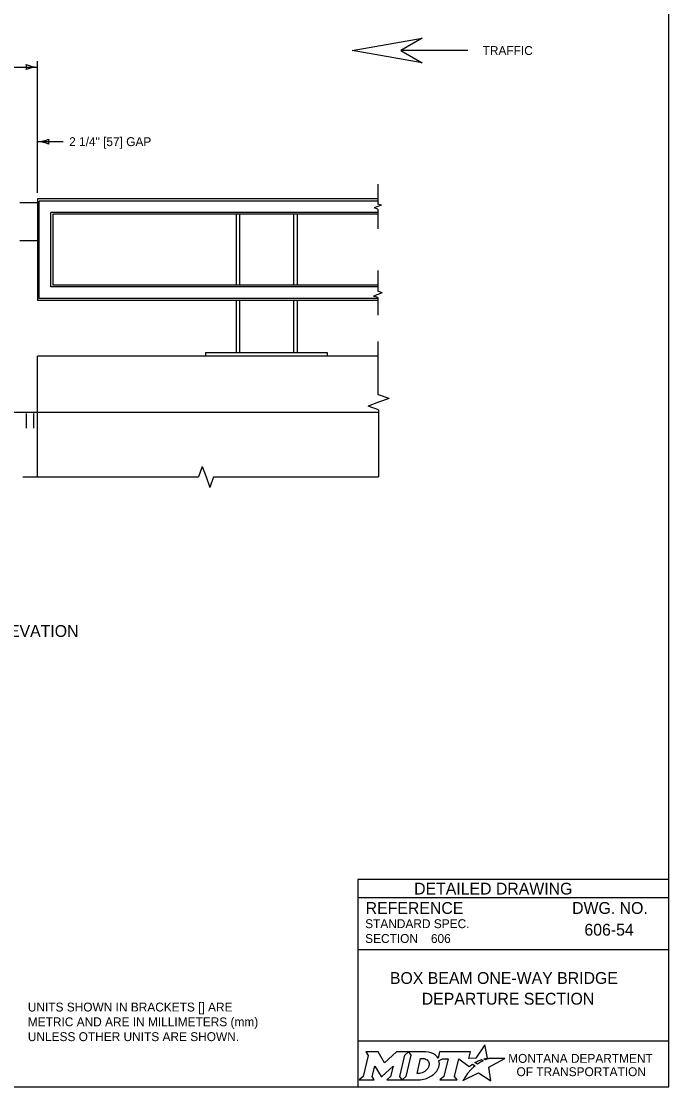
# Model space of a CAD drawing. Extents: x 49991.4 to 50021, y 49987.6 to 50011.4.
# Drawn here: x 50004.24 to 50008.61, y 50000.06 to 50007.26 of the extents above; entities that cross this region are included whole.
import ezdxf

# ---------------------------------------------------------------- set-up
doc = ezdxf.new("R2010")
doc.units = 0
for name, color, linetype in [('Level 1', 7, 'Continuous'), ('Level 2', 7, 'Continuous'), ('Level 3', 7, 'Continuous'), ('Level 4', 7, 'Continuous'), ('Level 6', 7, 'Continuous')]:
    doc.layers.add(name, color=color, linetype=linetype)

msp = doc.modelspace()

# ---------------------------------------------------------------- linework, layer by layer
at = {"layer": 'Level 1'}
for p, q in [((50007.2582, 50007.0589), (50006.8063, 50007.0589)), ((50007.2582, 50007.0585), (50006.8063, 50007.0585)), ((50006.6505, 50006.0572), (50004.3525, 50006.0572)), ((50004.3525, 50006.0572), (50004.3525, 50005.3714)), ((50004.3525, 50006.031), (50004.2333, 50006.031)), ((50004.4553, 50005.9543), (50004.4553, 50005.4743)), ((50006.6505, 50005.9543), (50004.4553, 50005.9543)), ((50005.6928, 50005.9543), (50005.6928, 50005.4743)), ((50005.7172, 50005.9543), (50005.7172, 50005.4743)), ((50006.0801, 50005.9543), (50006.0801, 50005.4743)), ((50006.1048, 50005.9543), (50006.1048, 50005.4743)), ((50004.3525, 50005.774), (50004.2333, 50005.774)), ((50006.6505, 50005.4743), (50004.4553, 50005.4743)), ((50006.6505, 50005.3714), (50004.3525, 50005.3714)), ((50005.6928, 50005.3714), (50005.6928, 50005.0209)), ((50005.7172, 50005.3714), (50005.7172, 50005.0209)), ((50006.0801, 50005.3714), (50006.0801, 50005.0209)), ((50006.1048, 50005.3714), (50006.1048, 50005.0209)), ((50006.6505, 50004.9951), (50004.3525, 50004.9951)), ((50004.3525, 50004.6177), (50004.3525, 50004.9951)), ((50005.4865, 50005.0209), (50006.3094, 50005.0209)), ((50005.4865, 50005.0209), (50005.4865, 50004.9951)), ((50006.3094, 50005.0209), (50006.3094, 50004.9951)), ((50001.9518, 50004.6177), (50006.6556, 50004.6177)), ((50004.279, 50004.5095), (50004.279, 50004.607)), ((50004.3278, 50004.5095), (50004.3278, 50004.607))]:
    msp.add_line(p, q, dxfattribs=at)
for points in [[(50008.6146, 50011.2628), (50000.3356, 50011.2628), (50000.3356, 50000.0624), (50008.6146, 50000.0624)], [(50006.9508, 50006.9751), (50006.4779, 50007.0585), (50006.9508, 50007.1423), (50006.8065, 50007.0585)]]:
    msp.add_lwpolyline(points, close=True, dxfattribs=at)
at = {"layer": 'Level 2'}
for p, q in [((50008.6146, 50001.4624), (50006.5146, 50001.4624)), ((50006.5146, 50001.4624), (50006.5146, 50000.0624)), ((50008.6146, 50001.3374), (50006.5146, 50001.3374)), ((50008.2507, 50001.1223), (50008.2507, 50001.1223)), ((50007.0089, 50001.0629), (50007.0089, 50001.0629)), ((50008.6146, 50000.9874), (50006.5146, 50000.9874)), ((50007.5646, 50000.7383), (50007.5646, 50000.7383)), ((50008.6146, 50000.3693), (50006.5146, 50000.3693))]:
    msp.add_line(p, q, dxfattribs=at)
for points in [[(50006.5701, 50000.2974), (50006.5842, 50000.274), (50006.5507, 50000.1307), (50006.525, 50000.1082), (50006.6266, 50000.1082), (50006.6131, 50000.131), (50006.6293, 50000.2011), (50006.673, 50000.1321), (50006.6783, 50000.1321), (50006.7534, 50000.2016), (50006.737, 50000.1305), (50006.7123, 50000.1085), (50006.8139, 50000.1085), (50006.8001, 50000.1318), (50006.8333, 50000.2742)], [(50006.8333, 50000.2742), (50006.8586, 50000.2974), (50006.7762, 50000.2974), (50006.6966, 50000.2244), (50006.6521, 50000.2971), (50006.5701, 50000.2974)], [(50006.9722, 50000.2974), (50006.8586, 50000.2974), (50006.8733, 50000.2745), (50006.8394, 50000.1307), (50006.8139, 50000.1085), (50006.9245, 50000.1085)], [(50007.3771, 50000.2447), (50007.3668, 50000.2503), (50007.3784, 50000.2531), (50007.39, 50000.2551), (50007.3726, 50000.3452), (50007.3131, 50000.2539), (50007.2658, 50000.2532), (50007.2761, 50000.2973), (50007.0669, 50000.2974), (50007.0568, 50000.2549), (50007.051, 50000.2632)], [(50006.9962, 50000.2107), (50006.995, 50000.2026), (50006.9918, 50000.1933), (50006.9876, 50000.1851), (50006.982, 50000.1776), (50006.9755, 50000.1707), (50006.9676, 50000.1644), (50006.9593, 50000.1597), (50006.9502, 50000.1558), (50006.9411, 50000.1535), (50006.9319, 50000.1526), (50006.916, 50000.1526), (50006.9396, 50000.2526), (50006.9556, 50000.2526), (50006.9632, 50000.252), (50006.9708, 50000.2501), (50006.9774, 50000.2471), (50006.9835, 50000.2429), (50006.9883, 50000.2379), (50006.992, 50000.2319), (50006.9947, 50000.2257), (50006.9963, 50000.2183), (50006.9963, 50000.2153), (50006.9962, 50000.2107)], [(50007.0636, 50000.2383), (50007.0882, 50000.2514), (50007.1251, 50000.2514), (50007.0965, 50000.1309), (50007.069, 50000.1082), (50007.1852, 50000.1082), (50007.1682, 50000.1311), (50007.1964, 50000.2513), (50007.2677, 50000.1996), (50007.2888, 50000.2147), (50007.3085, 50000.2038)], [(50007.2527, 50000.1479), (50007.2374, 50000.1235), (50007.2327, 50000.116), (50007.2269, 50000.1074), (50007.2246, 50000.1031), (50007.3299, 50000.1562), (50007.4138, 50000.1011), (50007.4007, 50000.1938), (50007.5076, 50000.2522), (50007.4583, 50000.253), (50007.4282, 50000.2534), (50007.4074, 50000.2537), (50007.4006, 50000.2522), (50007.3957, 50000.251), (50007.3873, 50000.2487), (50007.3771, 50000.2447)], [(50007.3267, 50000.2171), (50007.3243, 50000.2154), (50007.306, 50000.225), (50007.3163, 50000.2307), (50007.3204, 50000.2329), (50007.329, 50000.2369), (50007.3347, 50000.2395), (50007.3426, 50000.2425), (50007.3499, 50000.2452), (50007.3617, 50000.2378), (50007.3577, 50000.2357), (50007.3531, 50000.2332), (50007.3489, 50000.231), (50007.3439, 50000.2281), (50007.342, 50000.227), (50007.3393, 50000.2254), (50007.3368, 50000.224), (50007.3345, 50000.2224), (50007.3319, 50000.2206), (50007.3292, 50000.2188), (50007.3267, 50000.2171)], [(50007.2666, 50000.164), (50007.2666, 50000.164)], [(50006.9702, 50000.1158), (50006.9786, 50000.1184), (50006.9916, 50000.1238), (50007.012, 50000.1348)]]:
    msp.add_lwpolyline(points, dxfattribs=at)
for centre, radius, start, end in [((50006.9953, 50000.219), 0.0709, 339.53292, 15.85821), ((50006.9513, 50000.2363), 0.1183, 300.91025, 339.13831)]:
    msp.add_arc(centre, radius, start, end, dxfattribs=at)
for centre, major_axis, ratio, start_param, end_param in [((50006.9701, 50000.25), (0.0834, -0.0037), 0.568097, 0.61298, 1.570796), ((50007.0257, 50000.2573), (0.0361, -0.0295), 0.469099, 1.225588, 1.570796), ((50007.2597, 50000.1559), (-0.00694, -0.00806), 0.008222, 0, 3.137361), ((50007.2764, 50000.1742), (-0.0098, -0.0102), 0.016458, 3.141593, 6.279097), ((50007.2974, 50000.1941), (-0.0112, -0.0097), 0.021651, 3.157348, 6.283185), ((50006.9248, 50000.2568), (0, 0.1484), 0.987302, 3.139398, 3.456847)]:
    msp.add_ellipse(centre, major_axis=major_axis, ratio=ratio, start_param=start_param, end_param=end_param, dxfattribs=at)
at = {"layer": 'Level 3'}
for p, q in [((50004.3525, 50006.0972), (50004.3525, 50006.9869)), ((50002.4997, 50006.9469), (50004.3525, 50006.9469)), ((50004.3525, 50006.4436), (50004.5259, 50006.4436))]:
    msp.add_line(p, q, dxfattribs=at)
for centre, radius, start, end in [((50004.3617, 50007.1691), 0.2223, 247.45601, 267.63952), ((50004.2243, 50006.9469), 0.0548, 342.13882, 17.86118), ((50004.364, 50006.7142), 0.233, 92.82731, 112.07716), ((50004.3411, 50006.6763), 0.233, 272.82731, 292.07716), ((50004.3434, 50006.2214), 0.2223, 67.45601, 87.63952), ((50004.4808, 50006.4436), 0.0548, 162.13882, 197.86118)]:
    msp.add_arc(centre, radius, start, end, dxfattribs=at)
at = {"layer": 'Level 4'}
for p, q in [((50004.3644, 50005.3839), (50004.3644, 50006.0428)), ((50006.6505, 50006.0428), (50004.3644, 50006.0428)), ((50004.4434, 50005.4626), (50004.4434, 50005.9662)), ((50006.6505, 50005.9662), (50004.4434, 50005.9662)), ((50006.6505, 50005.4626), (50004.4434, 50005.4626)), ((50006.6505, 50005.3839), (50004.3644, 50005.3839)), ((50004.3525, 50004.1798), (50004.3525, 50004.6177))]:
    msp.add_line(p, q, dxfattribs=at)
at = {"layer": 'Level 6'}
for p, q in [((50006.6505, 50006.1572), (50006.6505, 50006.0226)), ((50006.6505, 50006.0049), (50006.6253, 50005.9957)), ((50006.6505, 50005.987), (50006.6253, 50005.9957)), ((50006.6759, 50006.0137), (50006.6505, 50006.0226)), ((50006.6759, 50006.0137), (50006.6505, 50006.0049)), ((50006.6505, 50005.987), (50006.6505, 50005.8543)), ((50006.6505, 50005.5743), (50006.6505, 50005.4331)), ((50006.6505, 50005.4121), (50006.6205, 50005.4013)), ((50006.6805, 50005.4226), (50006.6505, 50005.4331)), ((50006.6805, 50005.4226), (50006.6505, 50005.4121)), ((50006.6505, 50005.3908), (50006.6205, 50005.4013)), ((50006.6505, 50005.3908), (50006.6505, 50005.2714)), ((50006.6505, 50005.0951), (50006.6505, 50004.7338)), ((50006.6556, 50004.6835), (50006.5845, 50004.6582)), ((50006.7267, 50004.7087), (50006.6556, 50004.7338)), ((50006.7267, 50004.7087), (50006.6556, 50004.6835)), ((50006.6556, 50004.6331), (50006.5845, 50004.6582)), ((50006.6556, 50004.6331), (50006.6556, 50004.1798)), ((50004.2525, 50004.1798), (50005.44, 50004.1798)), ((50005.4651, 50004.2509), (50005.44, 50004.1798)), ((50005.4651, 50004.2509), (50005.4903, 50004.1798)), ((50005.4903, 50004.1798), (50005.5156, 50004.1087)), ((50005.5407, 50004.1798), (50005.5156, 50004.1087)), ((50005.5407, 50004.1798), (50006.6556, 50004.1798))]:
    msp.add_line(p, q, dxfattribs=at)

# ---------------------------------------------------------------- texts
at = {"layer": 'Level 2'}
for s, height, p in [('TRAFFIC', 0.06, (50007.3582, 50007.0289)), ('2 1/4" [57] GAP', 0.06, (50004.5659, 50006.4136)), ('ELEVATION', 0.08, (50004.0287, 50003.0994)), ('DETAILED DRAWING', 0.0799, (50006.8956, 50001.3599)), ('REFERENCE', 0.08, (50006.5682, 50001.229)), ('DWG. NO.', 0.08, (50007.9624, 50001.229)), ('STANDARD SPEC.', 0.06, (50006.5649, 50001.133)), ('606-54', 0.08, (50008.0456, 50001.0823)), ('SECTION', 0.06, (50006.5649, 50001.033)), ('606', 0.06, (50007.0089, 50001.0329)), ('BOX BEAM ONE-WAY BRIDGE ', 0.08, (50006.732, 50000.7563)), ('DEPARTURE SECTION', 0.08, (50006.9469, 50000.6163)), ('UNITS SHOWN IN BRACKETS [] ARE ', 0.06, (50004.287, 50000.5702)), ('METRIC AND ARE IN MILLIMETERS (mm) ', 0.06, (50004.287, 50000.4702)), ('UNLESS OTHER UNITS ARE SHOWN.', 0.06, (50004.287, 50000.3702)), ('MONTANA DEPARTMENT', 0.06, (50007.5308, 50000.2236)), ('OF TRANSPORTATION', 0.06, (50007.587, 50000.1336))]:
    msp.add_text(s, height=height, dxfattribs=at).set_placement(p)

doc.saveas('drawing.dxf')
